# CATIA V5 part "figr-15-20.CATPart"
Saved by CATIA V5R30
Part number: Part1
Bounding box of the stored display mesh (mm): x -81.56 to 85.56, y -36.965 to 25.965, z 0 to 42
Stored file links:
  D:\PROJECTS\CATIA V56R 2020\Resources\Parts File\c15_catia_v5_6r2020_prt\figr-15-20.CATPart
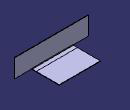
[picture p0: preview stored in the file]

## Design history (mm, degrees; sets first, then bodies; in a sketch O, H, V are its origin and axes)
SheetMetalParameters1: Thickness 1, BendRadius 1, KFactor 0.325257 {= log(min(100,max(20*SheetMetalParameters1.BendRadius,SheetMetalParameters1.Thickness)/SheetMetalParameters1.Thickness))/log(100)/2}, ReliefRadialLength 1, ReliefAxialLength 2, MinimumBendRadius 0
Body1 (main body)
  Sketch1 on xy-plane, origin (0, 0, 0), H (1, 0, 0), V (0, 1, 0)
    line L1 (-46.5596, 25.9646) -> (46.5596, 25.9646)
    line L2 (46.5596, 25.9646) -> (46.5596, -25.9646)
    line L3 (46.5596, -25.9646) -> (-46.5596, -25.9646)
    line L4 (-46.5596, -25.9646) -> (-46.5596, 25.9646)
    horizontal: L1 H, L3 H
    vertical: L2 V, L4 V
    symmetry: L1 L3 H, L4 L2 V
  Wall1: Thickness 1, Profile Sketch1
  d_NewWallOnEdge1: NewWallOnEdge_Edge edge [face of Wall1 | face of Wall1], NewWallOnEdge_Length 42, NewWallOnEdge_HeightLimitOffset 0, NewWallOnEdge_WidthOffset1 39, NewWallOnEdge_WidthOffset2 35, NewWallOnEdge_Angle 90, NewWallOnEdge_BendRadiusValue 1 {= SheetMetalParameters1.BendRadius}, NewWallOnEdge_BendTable SheetMetalParameters1, KFacteur 0.325257 {= log(min(100,max(20*d_NewWallOnEdge1.Radius,SheetMetalParameters1.Thickness)/SheetMetalParameters1.Thickness))/log(100)/2}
